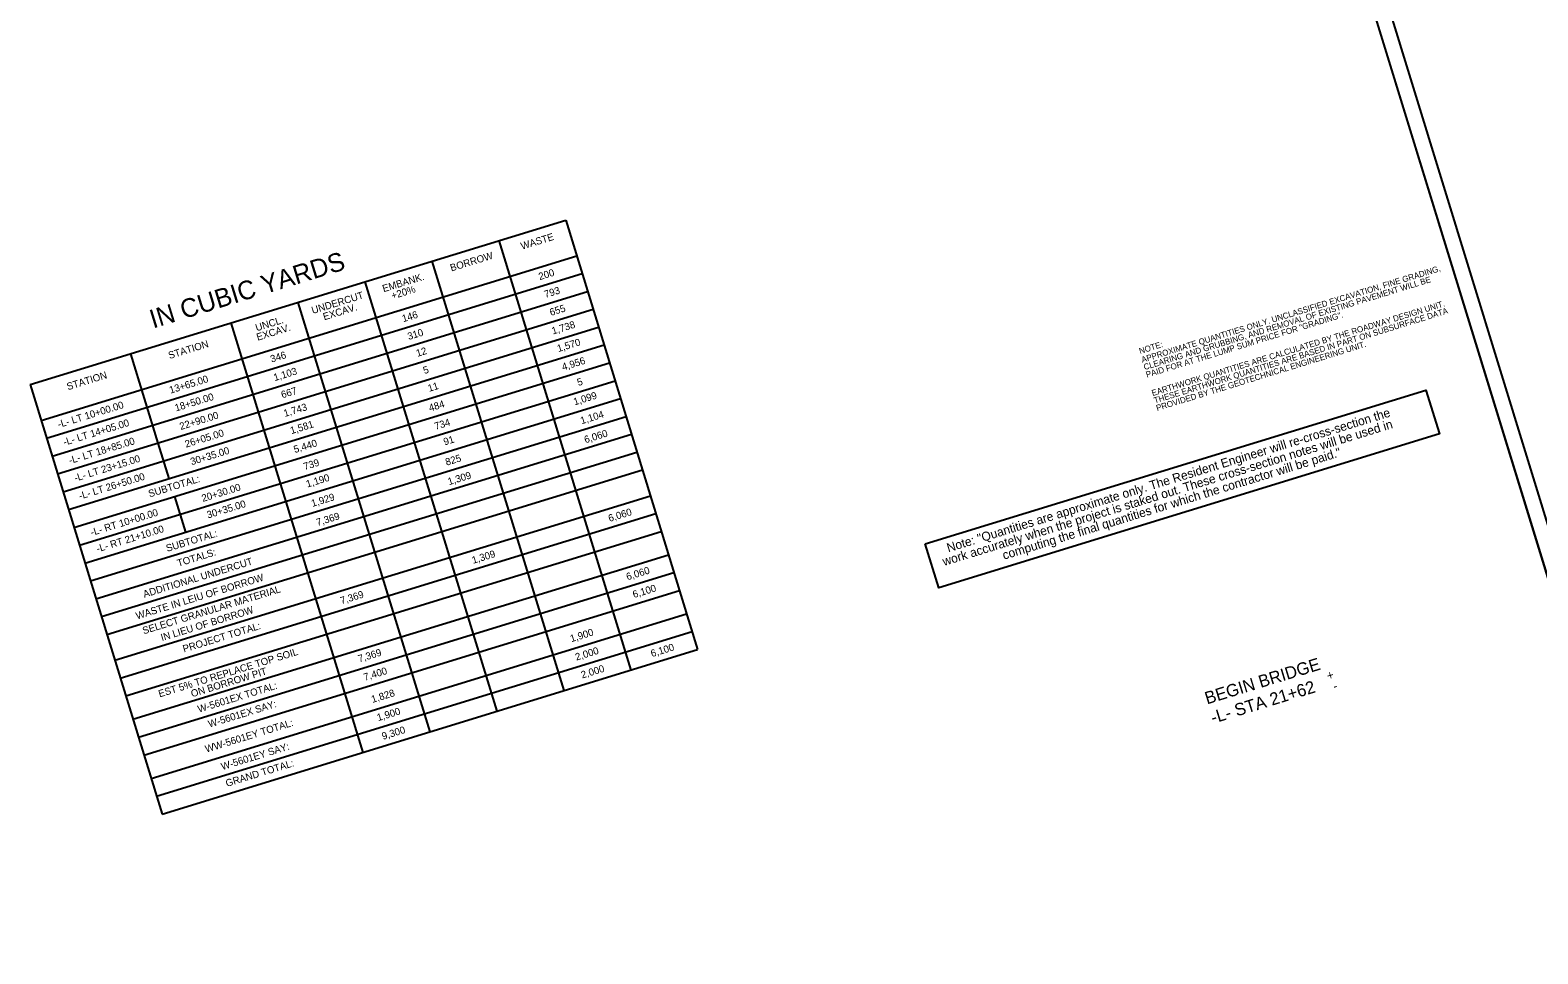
# Model space of a CAD drawing. Extents: x 2528815 to 2532488, y 739965 to 742287.
# Drawn here: x 2528815 to 2530077, y 740649 to 741422 of the extents above; entities that cross this region are included whole.
import ezdxf

# ---------------------------------------------------------------- set-up
doc = ezdxf.new("R2010")
doc.units = 0
for name, color, linetype in [('Prop Dimension Text', 7, 'Continuous'), ('Prop Grid Mask', 7, 'Continuous'), ('Prop XSC Text', 7, 'Continuous'), ('Sheet Cutting Line CELL', 7, 'Continuous'), ('Sheet Plot Border Inside CELL', 7, 'Continuous'), ('Sheet Plot Border Outside CELL', 7, 'Continuous'), ('Sheet Summary Combination CELL', 7, 'Continuous'), ('Sheet Summary Combination Grid CELL', 7, 'Continuous'), ('Sheet Summary Earthwork CELL', 7, 'Continuous')]:
    doc.layers.add(name, color=color, linetype=linetype)

msp = doc.modelspace()

# ---------------------------------------------------------------- linework, layer by layer
at = {"layer": 'Prop Grid Mask'}
msp.add_lwpolyline([(2529564.1, 740992.2), (2529983.1, 741121), (2529994.4, 741084.3), (2529575.4, 740955.5)], close=True, dxfattribs=at)
at = {"layer": 'Sheet Cutting Line CELL'}
msp.add_line((2529858.7, 741700.6), (2530181.8, 740649.1), dxfattribs=at)
at = {"layer": 'Sheet Plot Border Inside CELL'}
msp.add_lwpolyline([(2531470.7, 742172.5), (2529877.7, 741682.9), (2530187.7, 740674.4), (2531780.6, 741163.9)], close=True, dxfattribs=at)
at = {"layer": 'Sheet Plot Border Outside CELL'}
msp.add_lwpolyline([(2531468.4, 742195.3), (2529858.7, 741700.6), (2530181.8, 740649.1), (2531791.5, 741143.8)], close=True, dxfattribs=at)
at = {"layer": 'Sheet Summary Combination CELL'}
for p, q in [((2528935.1, 741162.2), (2528935.1, 741162.2)), ((2528945.8, 741165.8), (2528945.8, 741165.8)), ((2528952.6, 741167.7), (2528952.6, 741167.7)), ((2528927.6, 741160.1), (2528927.6, 741160.1))]:
    msp.add_line(p, q, dxfattribs=at)
at = {"layer": 'Sheet Summary Combination Grid CELL'}
for p, q in [((2528814.8, 741125.5), (2529263.1, 741263.2)), ((2529263.1, 741263.2), (2529373.5, 740903.8)), ((2529207, 741246), (2529317.5, 740886.6)), ((2529207, 741246), (2529207, 741246)), ((2528824, 741095.6), (2529272.3, 741233.4)), ((2529151, 741228.8), (2529261.4, 740869.4)), ((2528828.6, 741080.7), (2529276.8, 741218.4)), ((2528833.2, 741065.7), (2529281.4, 741203.5)), ((2529095, 741211.6), (2529205.4, 740852.2)), ((2528837.8, 741050.8), (2529286, 741188.6)), ((2529038.9, 741194.3), (2529149.4, 740834.9)), ((2528982.9, 741177.1), (2529093.3, 740817.7)), ((2528842.4, 741035.9), (2529290.6, 741173.6)), ((2528847, 741020.9), (2529295.2, 741158.7)), ((2528847, 741020.9), (2529295.2, 741158.7)), ((2528898.9, 741151.3), (2528921.8, 741076.6)), ((2528851.5, 741006), (2529299.8, 741143.7)), ((2528814.8, 741125.5), (2528925.3, 740766.1)), ((2528856.1, 740991.1), (2529304.4, 741128.8)), ((2528860.7, 740976.1), (2529309, 741113.9)), ((2528860.7, 740976.1), (2529309, 741113.9)), ((2528865.3, 740961.2), (2529313.6, 741098.9)), ((2528869.9, 740946.2), (2529318.2, 741084)), ((2528921.8, 741076.6), (2528931, 741046.8)), ((2528874.5, 740931.3), (2529322.7, 741069.1)), ((2528879.1, 740916.4), (2529327.3, 741054.1)), ((2528885.7, 740894.8), (2529334, 741032.5)), ((2528935.6, 741031.8), (2528944.8, 741002)), ((2528890.3, 740879.9), (2529338.6, 741017.6)), ((2528894.9, 740864.9), (2529343.1, 741002.7)), ((2528900.9, 740845.4), (2529349.2, 740983.1)), ((2528905.5, 740830.4), (2529353.7, 740968.2)), ((2528910.1, 740815.5), (2529358.3, 740953.3)), ((2528916.1, 740795.9), (2529364.3, 740933.7)), ((2528920.7, 740781), (2529368.9, 740918.8)), ((2528920.7, 740781), (2529368.9, 740918.8)), ((2528925.3, 740766.1), (2529373.5, 740903.8)), ((2528925.3, 740766.1), (2529373.5, 740903.8))]:
    msp.add_line(p, q, dxfattribs=at)

# ---------------------------------------------------------------- texts
at = {"layer": 'Prop Dimension Text'}
for s, height, p in [('BEGIN BRIDGE', 10.369, (2529799.9, 740857.8)), ('+', 7.26, (2529901.4, 740878)), ('-L- STA 21+62', 10.369, (2529804.9, 740841.6)), ('-', 7.26, (2529906.6, 740869.4))]:
    msp.add_text(s, height=height, rotation=17.0725, dxfattribs=at).set_placement(p)
at = {"layer": 'Prop XSC Text'}
for s, p in [('Note: "Quantities are approximate only. The Resident Engineer will re-cross-section the', (2529583.4, 740985.1)), ('work accurately when the project is staked out. These cross-section notes will be used in', (2529579.8, 740973.7)), ('computing the final quantities for which the contractor will be paid."', (2529630, 740978.9))]:
    msp.add_text(s, height=7.5, rotation=17.0832, dxfattribs=at).set_placement(p)
at = {"layer": 'Sheet Summary Combination CELL'}
for s, height, rotation, p in [('WASTE', 6, 17.0832, (2529226.5, 741238.4)), ('IN CUBIC YARDS', 15.625, 17.0952, (2528917.7, 741172.4)), ('BORROW', 6, 17.0832, (2529167.4, 741220.2)), ('EMBANK.', 6, 17.0832, (2529110.7, 741202.8)), ('200', 6, 17.0832, (2529241.4, 741212.9)), ('APPROXIMATE QUANTITIES ONLY. UNCLASSIFIED EXCAVATION, FINE GRADING,', 5, 17.0832, (2529745.8, 741143.8)), ('CLEARING AND GRUBBING, AND REMOVAL OF EXISTING PAVEMENT WILL BE ', 5, 17.0832, (2529747.7, 741137.6)), ('UNDERCUT', 6, 17.0832, (2529051.4, 741184.6)), ('+20%', 6, 17.0832, (2529118.1, 741196.8)), ('793', 6, 17.0832, (2529246.1, 741198)), ('EXCAV.', 6, 17.0832, (2529061, 741179.3)), ('146', 6, 17.0832, (2529127.1, 741177.7)), ('655', 6, 17.0832, (2529250.7, 741183)), ('UNCL.', 6, 17.0832, (2529004.4, 741170.1)), ('EXCAV.', 6, 17.0832, (2529005.3, 741162.2)), ('1,738', 6, 17.0832, (2529252.4, 741167.4)), ('PAID FOR AT THE LUMP SUM PRICE FOR "GRADING".', 5, 17.0832, (2529749.6, 741131.3)), ('STATION', 6, 17.0832, (2528931.5, 741146.9)), ('310', 6, 17.0832, (2529131.7, 741162.8)), ('1,570', 6, 17.0832, (2529256.9, 741152.7)), ('346', 6, 17.0832, (2529016.9, 741143.9)), ('12', 6, 17.0832, (2529138.9, 741148.7)), ('NOTE:', 5, 17.0832, (2529743.9, 741151.1)), ('STATION', 6, 17.0832, (2528846.5, 741120.8)), ('1,103', 6, 17.0832, (2529019.6, 741128.4)), ('5', 6, 17.0832, (2529144.8, 741134.3)), ('4,956', 6, 17.0832, (2529260.9, 741137.2)), ('13+65.00', 6, 17.0832, (2528932.3, 741117.9)), ('11', 6, 17.0832, (2529148.7, 741119.4)), ('5', 6, 17.0832, (2529273.7, 741124.3)), ('-L- LT 10+00.00', 6, 17.0832, (2528838.9, 741089.2)), ('18+50.00', 6, 17.0832, (2528936.9, 741103)), ('667', 6, 17.0832, (2529025.9, 741114)), ('484', 6, 17.0832, (2529149.5, 741102.9)), ('1,099', 6, 17.0832, (2529270.6, 741108.1)), ('22+90.00', 6, 17.0832, (2528940.9, 741087.5)), ('1,743', 6, 17.0832, (2529028, 741098.4)), ('1,104', 6, 17.0832, (2529276.4, 741092.3)), ('-L- LT 14+05.00', 6, 17.0832, (2528843.5, 741074.3)), ('26+05.00', 6, 17.0832, (2528945.4, 741072.7)), ('1,581', 6, 17.0832, (2529033.5, 741084)), ('734', 6, 17.0832, (2529154.2, 741087.6)), ('6,060', 6, 17.0832, (2529279.6, 741076.4)), ('-L- LT 18+85.00', 6, 17.0832, (2528848.2, 741059)), ('30+35.00', 6, 17.0832, (2528950, 741058)), ('5,440', 6, 17.0832, (2529036.4, 741068.2)), ('91', 6, 17.0832, (2529161.8, 741074.6)), ('-L- LT 23+15.00', 6, 17.0832, (2528852.7, 741044.3)), ('739', 6, 17.0832, (2529044.6, 741053.9)), ('825', 6, 17.0832, (2529163.4, 741057.6)), ('-L- LT 26+50.00', 6, 17.0832, (2528856.6, 741029.3)), ('SUBTOTAL:', 6, 17.0832, (2528914.8, 741031.1)), ('1,190', 6, 17.0832, (2529046.8, 741039.3)), ('1,309', 6, 17.0832, (2529165.4, 741041.3)), ('20+30.00', 6, 17.0832, (2528959.4, 741027.3)), ('30+35.00', 6, 17.0832, (2528963.7, 741013.4)), ('1,929', 6, 17.0832, (2529051.1, 741023.1)), ('-L- RT 10+00.00', 6, 17.0832, (2528866.4, 740998.8)), ('7,369', 6, 17.0832, (2529055.3, 741007.1)), ('6,060', 6, 17.0832, (2529299.8, 741010.6)), ('-L- RT 21+10.00', 6, 17.0832, (2528871.3, 740985.1)), ('SUBTOTAL:', 6, 17.0832, (2528929.6, 740985.5)), ('TOTALS:', 6, 17.0832, (2528938.9, 740973)), ('1,309', 6, 17.0832, (2529185.6, 740975.5)), ('ADDITIONAL UNDERCUT', 6, 17.0832, (2528910.4, 740947.1)), ('6,060', 6, 17.0832, (2529314.8, 740961.7)), ('WASTE IN LEIU OF BORROW', 6, 17.0832, (2528904.3, 740928.9)), ('SELECT GRANULAR MATERIAL', 6, 17.0832, (2528909.9, 740916.5)), ('7,369', 6, 17.0832, (2529075.4, 740941.6)), ('6,100', 6, 17.0832, (2529320.2, 740946.8)), ('IN LIEU OF BORROW', 6, 17.0832, (2528925.2, 740910.8)), ('PROJECT TOTAL:', 6, 17.0832, (2528943.6, 740901.3)), ('1,900', 6, 17.0832, (2529267.8, 740909.9)), ('EST 5% TO REPLACE TOP SOIL', 6, 17.0832, (2528923.2, 740863.7)), ('7,369', 6, 17.0832, (2529090.3, 740893)), ('2,000', 6, 17.0832, (2529272.1, 740894.5)), ('6,100', 6, 17.0832, (2529335.3, 740897.4)), ('ON BORROW PIT', 6, 17.0832, (2528950.4, 740863.8)), ('7,400', 6, 17.0832, (2529095, 740877.6)), ('2,000', 6, 17.0832, (2529276.9, 740879.5)), ('W-5601EX TOTAL:', 6, 17.0832, (2528956.1, 740850.9)), ('W-5601EX SAY:', 6, 17.0832, (2528964.9, 740838.4)), ('1,828', 6, 17.0832, (2529101.4, 740859.1)), ('1,900', 6, 17.0832, (2529106.1, 740843.8)), ('WW-5601EY TOTAL:', 6, 17.0832, (2528962.3, 740817.5)), ('9,300', 6, 17.0832, (2529110.2, 740828.2)), ('W-5601EY SAY:', 6, 17.0832, (2528975.7, 740802.8)), ('GRAND TOTAL:', 6, 17.0832, (2528979.5, 740788.8))]:
    msp.add_text(s, height=height, rotation=rotation, dxfattribs=at).set_placement(p)
at = {"layer": 'Sheet Summary Earthwork CELL'}
for s, p in [('EARTHWORK QUANTITIES ARE CALCULATED BY THE ROADWAY DESIGN UNIT. ', (2529754.4, 741115.9)), ('THESE EARTHWORK QUANTITIES ARE BASED IN PART ON SUBSURFACE DATA ', (2529756.3, 741109.7)), ('PROVIDED BY THE GEOTECHNICAL ENGINEERING UNIT.', (2529758.2, 741103.4))]:
    msp.add_text(s, height=5, rotation=17.0832, dxfattribs=at).set_placement(p)

doc.saveas('drawing.dxf')
